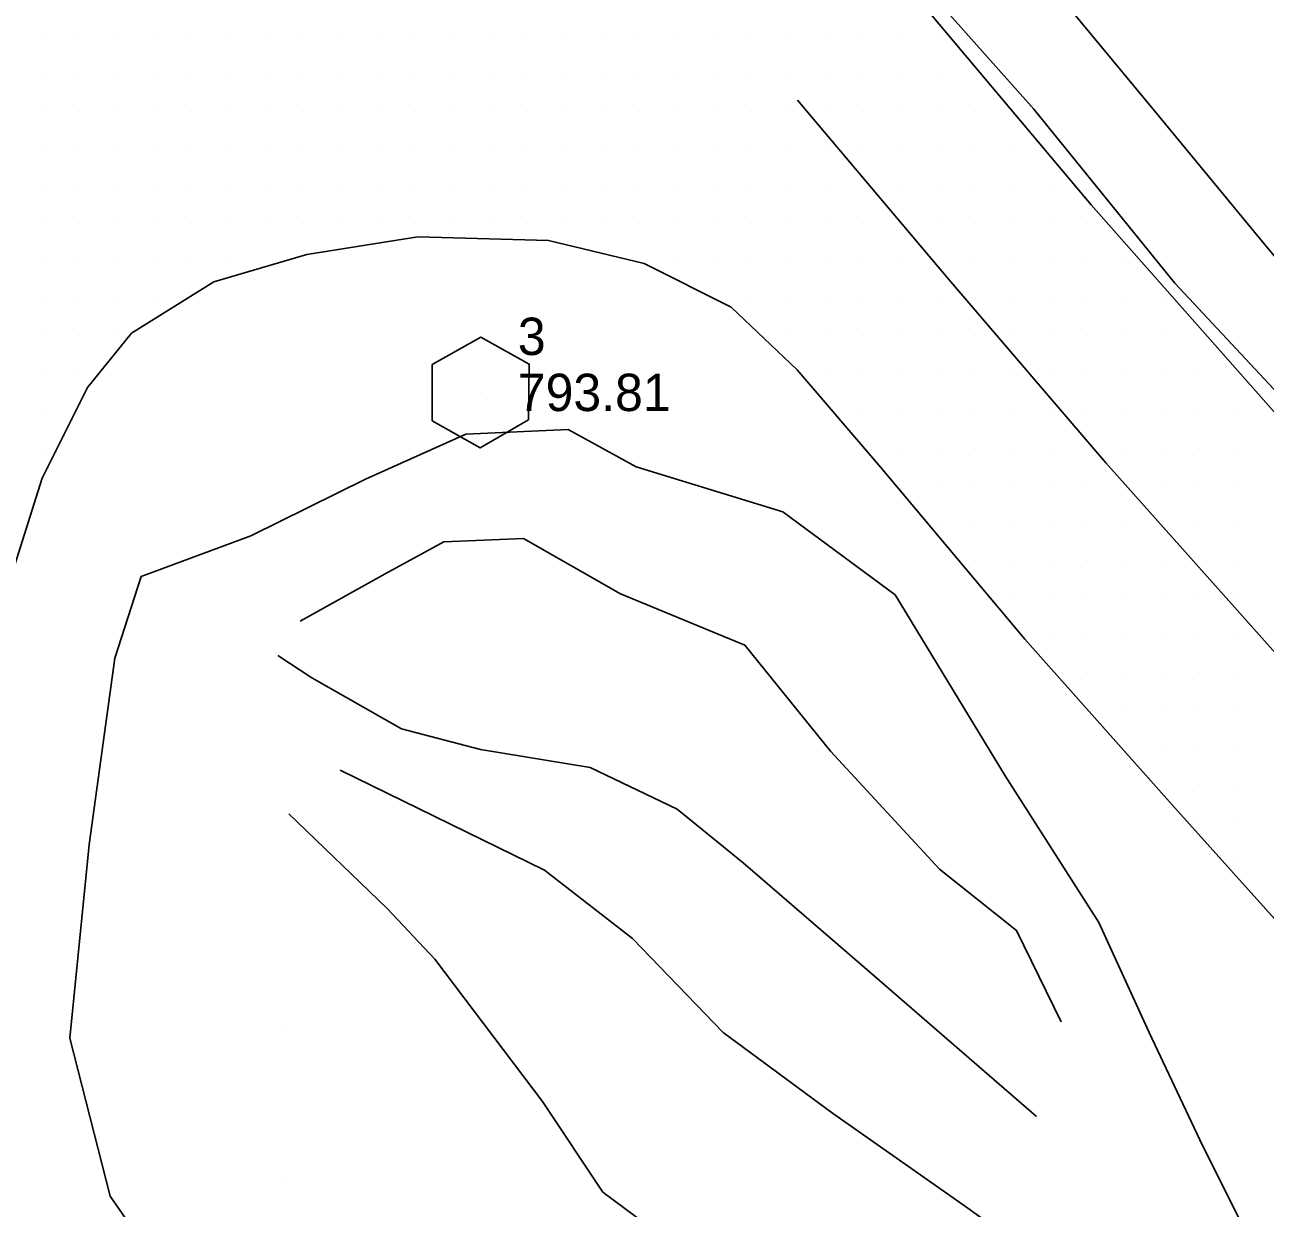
# Model space of a CAD drawing. Extents: x 1762120 to 1766775, y 709485 to 712965.
# Drawn here: x 1764097.6 to 1764180.6, y 711242.9 to 711322.1 of the extents above; entities that cross this region are included whole.
import ezdxf

# ---------------------------------------------------------------- set-up
doc = ezdxf.new("R2010")
doc.units = 0
for name, color, linetype in [('CTL Primary Horizontal and Vertical CELL', 7, 'Continuous'), ('CTL Primary Horizontal and Vertical Cogo Elevation', 7, 'Continuous'), ('CTL Primary Horizontal and Vertical Cogo Number', 7, 'Continuous'), ('Exist DTM QL2 LIDAR Elevation Point', 7, 'Continuous'), ('Exist DTM Scan Elevation Point', 7, 'Continuous'), ('Exist Roads EOP', 7, 'Continuous'), ('Exist Roads EOT', 7, 'Continuous'), ('PH Exist DTM Breakline', 7, 'Continuous')]:
    doc.layers.add(name, color=color, linetype=linetype)

msp = doc.modelspace()

# ---------------------------------------------------------------- linework, layer by layer
at = {"layer": 'CTL Primary Horizontal and Vertical CELL'}
msp.add_line((1764128.102, 711297.478), (1764128.102, 711297.478), dxfattribs=at)
msp.add_lwpolyline([(1764124.871, 711299.35), (1764128.121, 711301.162), (1764131.371, 711299.375), (1764131.321, 711295.65), (1764128.071, 711293.762), (1764124.871, 711295.575)], close=True, dxfattribs=at)
at = {"layer": 'Exist DTM QL2 LIDAR Elevation Point'}
for p, q in [((1764114.998, 711254.994), (1764114.998, 711254.994)), ((1764114.998, 711244.993), (1764114.998, 711244.993))]:
    msp.add_line(p, q, dxfattribs=at)
at = {"layer": 'Exist DTM Scan Elevation Point'}
for p, q in [((1764098.75, 711321.25), (1764098.75, 711321.25)), ((1764101.25, 711321.25), (1764101.25, 711321.25)), ((1764103.75, 711321.25), (1764103.75, 711321.25)), ((1764106.25, 711321.25), (1764106.25, 711321.25)), ((1764108.75, 711321.25), (1764108.75, 711321.25)), ((1764111.25, 711321.25), (1764111.25, 711321.25)), ((1764113.75, 711321.25), (1764113.75, 711321.25)), ((1764116.25, 711321.25), (1764116.25, 711321.25)), ((1764118.75, 711321.25), (1764118.75, 711321.25)), ((1764121.25, 711321.25), (1764121.25, 711321.25)), ((1764123.75, 711321.25), (1764123.75, 711321.25)), ((1764126.25, 711321.25), (1764126.25, 711321.25)), ((1764128.75, 711321.25), (1764128.75, 711321.25)), ((1764131.25, 711321.25), (1764131.25, 711321.25)), ((1764133.75, 711321.25), (1764133.75, 711321.25)), ((1764136.25, 711321.25), (1764136.25, 711321.25)), ((1764138.75, 711321.25), (1764138.75, 711321.25)), ((1764141.25, 711321.25), (1764141.25, 711321.25)), ((1764143.75, 711321.25), (1764143.75, 711321.25)), ((1764146.25, 711321.25), (1764146.25, 711321.25)), ((1764148.75, 711321.25), (1764148.75, 711321.25)), ((1764151.25, 711321.25), (1764151.25, 711321.25)), ((1764153.75, 711321.25), (1764153.75, 711321.25)), ((1764156.25, 711321.25), (1764156.25, 711321.25)), ((1764158.75, 711321.25), (1764158.75, 711321.25)), ((1764098.75, 711318.75), (1764098.75, 711318.75)), ((1764101.25, 711318.75), (1764101.25, 711318.75)), ((1764103.75, 711318.75), (1764103.75, 711318.75)), ((1764106.25, 711318.75), (1764106.25, 711318.75)), ((1764108.75, 711318.75), (1764108.75, 711318.75)), ((1764111.25, 711318.75), (1764111.25, 711318.75)), ((1764113.75, 711318.75), (1764113.75, 711318.75)), ((1764116.25, 711318.75), (1764116.25, 711318.75)), ((1764118.75, 711318.75), (1764118.75, 711318.75)), ((1764121.25, 711318.75), (1764121.25, 711318.75)), ((1764123.75, 711318.75), (1764123.75, 711318.75)), ((1764126.25, 711318.75), (1764126.25, 711318.75)), ((1764128.75, 711318.75), (1764128.75, 711318.75)), ((1764131.25, 711318.75), (1764131.25, 711318.75)), ((1764133.75, 711318.75), (1764133.75, 711318.75)), ((1764136.25, 711318.75), (1764136.25, 711318.75)), ((1764138.75, 711318.75), (1764138.75, 711318.75)), ((1764141.25, 711318.75), (1764141.25, 711318.75)), ((1764143.75, 711318.75), (1764143.75, 711318.75)), ((1764146.25, 711318.75), (1764146.25, 711318.75)), ((1764148.75, 711318.75), (1764148.75, 711318.75)), ((1764151.25, 711318.75), (1764151.25, 711318.75)), ((1764153.75, 711318.75), (1764153.75, 711318.75)), ((1764156.25, 711318.75), (1764156.25, 711318.75)), ((1764158.75, 711318.75), (1764158.75, 711318.75)), ((1764098.75, 711316.25), (1764098.75, 711316.25)), ((1764101.25, 711316.25), (1764101.25, 711316.25)), ((1764103.75, 711316.25), (1764103.75, 711316.25)), ((1764106.25, 711316.25), (1764106.25, 711316.25)), ((1764108.75, 711316.25), (1764108.75, 711316.25)), ((1764111.25, 711316.25), (1764111.25, 711316.25)), ((1764113.75, 711316.25), (1764113.75, 711316.25)), ((1764116.25, 711316.25), (1764116.25, 711316.25)), ((1764118.75, 711316.25), (1764118.75, 711316.25)), ((1764121.25, 711316.25), (1764121.25, 711316.25)), ((1764123.75, 711316.25), (1764123.75, 711316.25)), ((1764126.25, 711316.25), (1764126.25, 711316.25)), ((1764128.75, 711316.25), (1764128.75, 711316.25)), ((1764131.25, 711316.25), (1764131.25, 711316.25)), ((1764133.75, 711316.25), (1764133.75, 711316.25)), ((1764136.25, 711316.25), (1764136.25, 711316.25)), ((1764138.75, 711316.25), (1764138.75, 711316.25)), ((1764141.25, 711316.25), (1764141.25, 711316.25)), ((1764143.75, 711316.25), (1764143.75, 711316.25)), ((1764146.25, 711316.25), (1764146.25, 711316.25)), ((1764148.75, 711316.25), (1764148.75, 711316.25)), ((1764151.25, 711316.25), (1764151.25, 711316.25)), ((1764153.75, 711316.25), (1764153.75, 711316.25)), ((1764156.25, 711316.25), (1764156.25, 711316.25)), ((1764158.75, 711316.25), (1764158.75, 711316.25)), ((1764161.25, 711316.25), (1764161.25, 711316.25)), ((1764098.75, 711313.75), (1764098.75, 711313.75)), ((1764101.25, 711313.75), (1764101.25, 711313.75)), ((1764103.75, 711313.75), (1764103.75, 711313.75)), ((1764106.25, 711313.75), (1764106.25, 711313.75)), ((1764108.75, 711313.75), (1764108.75, 711313.75)), ((1764111.25, 711313.75), (1764111.25, 711313.75)), ((1764113.75, 711313.75), (1764113.75, 711313.75)), ((1764116.25, 711313.75), (1764116.25, 711313.75)), ((1764118.75, 711313.75), (1764118.75, 711313.75)), ((1764121.25, 711313.75), (1764121.25, 711313.75)), ((1764123.75, 711313.75), (1764123.75, 711313.75)), ((1764126.25, 711313.75), (1764126.25, 711313.75)), ((1764128.75, 711313.75), (1764128.75, 711313.75)), ((1764131.25, 711313.75), (1764131.25, 711313.75)), ((1764133.75, 711313.75), (1764133.75, 711313.75)), ((1764136.25, 711313.75), (1764136.25, 711313.75)), ((1764138.75, 711313.75), (1764138.75, 711313.75)), ((1764141.25, 711313.75), (1764141.25, 711313.75)), ((1764143.75, 711313.75), (1764143.75, 711313.75)), ((1764146.25, 711313.75), (1764146.25, 711313.75)), ((1764148.75, 711313.75), (1764148.75, 711313.75)), ((1764151.25, 711313.75), (1764151.25, 711313.75)), ((1764153.75, 711313.75), (1764153.75, 711313.75)), ((1764156.25, 711313.75), (1764156.25, 711313.75)), ((1764158.75, 711313.75), (1764158.75, 711313.75)), ((1764161.25, 711313.75), (1764161.25, 711313.75)), ((1764163.75, 711313.75), (1764163.75, 711313.75)), ((1764098.75, 711311.25), (1764098.75, 711311.25)), ((1764101.25, 711311.25), (1764101.25, 711311.25)), ((1764103.75, 711311.25), (1764103.75, 711311.25)), ((1764106.25, 711311.25), (1764106.25, 711311.25)), ((1764108.75, 711311.25), (1764108.75, 711311.25)), ((1764111.25, 711311.25), (1764111.25, 711311.25)), ((1764113.75, 711311.25), (1764113.75, 711311.25)), ((1764116.25, 711311.25), (1764116.25, 711311.25)), ((1764118.75, 711311.25), (1764118.75, 711311.25)), ((1764121.25, 711311.25), (1764121.25, 711311.25)), ((1764123.75, 711311.25), (1764123.75, 711311.25)), ((1764126.25, 711311.25), (1764126.25, 711311.25)), ((1764128.75, 711311.25), (1764128.75, 711311.25)), ((1764131.25, 711311.25), (1764131.25, 711311.25)), ((1764133.75, 711311.25), (1764133.75, 711311.25)), ((1764136.25, 711311.25), (1764136.25, 711311.25)), ((1764138.75, 711311.25), (1764138.75, 711311.25)), ((1764141.25, 711311.25), (1764141.25, 711311.25)), ((1764143.75, 711311.25), (1764143.75, 711311.25)), ((1764146.25, 711311.25), (1764146.25, 711311.25)), ((1764148.75, 711311.25), (1764148.75, 711311.25)), ((1764151.25, 711311.25), (1764151.25, 711311.25)), ((1764156.25, 711311.25), (1764156.25, 711311.25)), ((1764158.75, 711311.25), (1764158.75, 711311.25)), ((1764161.25, 711311.25), (1764161.25, 711311.25)), ((1764163.75, 711311.25), (1764163.75, 711311.25)), ((1764166.25, 711311.25), (1764166.25, 711311.25)), ((1764098.75, 711308.75), (1764098.75, 711308.75)), ((1764101.25, 711308.75), (1764101.25, 711308.75)), ((1764103.75, 711308.75), (1764103.75, 711308.75)), ((1764106.25, 711308.75), (1764106.25, 711308.75)), ((1764108.75, 711308.75), (1764108.75, 711308.75)), ((1764111.25, 711308.75), (1764111.25, 711308.75)), ((1764113.75, 711308.75), (1764113.75, 711308.75)), ((1764116.25, 711308.75), (1764116.25, 711308.75)), ((1764118.75, 711308.75), (1764118.75, 711308.75)), ((1764121.25, 711308.75), (1764121.25, 711308.75)), ((1764123.75, 711308.75), (1764123.75, 711308.75)), ((1764126.25, 711308.75), (1764126.25, 711308.75)), ((1764128.75, 711308.75), (1764128.75, 711308.75)), ((1764131.25, 711308.75), (1764131.25, 711308.75)), ((1764133.75, 711308.75), (1764133.75, 711308.75)), ((1764136.25, 711308.75), (1764136.25, 711308.75)), ((1764138.75, 711308.75), (1764138.75, 711308.75)), ((1764141.25, 711308.75), (1764141.25, 711308.75)), ((1764143.75, 711308.75), (1764143.75, 711308.75)), ((1764146.25, 711308.75), (1764146.25, 711308.75)), ((1764148.75, 711308.75), (1764148.75, 711308.75)), ((1764151.25, 711308.75), (1764151.25, 711308.75)), ((1764153.75, 711308.75), (1764153.75, 711308.75)), ((1764158.75, 711308.75), (1764158.75, 711308.75)), ((1764161.25, 711308.75), (1764161.25, 711308.75)), ((1764163.75, 711308.75), (1764163.75, 711308.75)), ((1764166.25, 711308.75), (1764166.25, 711308.75)), ((1764168.75, 711308.75), (1764168.75, 711308.75)), ((1764098.75, 711306.25), (1764098.75, 711306.25)), ((1764101.25, 711306.25), (1764101.25, 711306.25)), ((1764103.75, 711306.25), (1764103.75, 711306.25)), ((1764106.25, 711306.25), (1764106.25, 711306.25)), ((1764108.75, 711306.25), (1764108.75, 711306.25)), ((1764111.25, 711306.25), (1764111.25, 711306.25)), ((1764141.25, 711306.25), (1764141.25, 711306.25)), ((1764143.75, 711306.25), (1764143.75, 711306.25)), ((1764146.25, 711306.25), (1764146.25, 711306.25)), ((1764148.75, 711306.25), (1764148.75, 711306.25)), ((1764151.25, 711306.25), (1764151.25, 711306.25)), ((1764153.75, 711306.25), (1764153.75, 711306.25)), ((1764156.25, 711306.25), (1764156.25, 711306.25)), ((1764161.25, 711306.25), (1764161.25, 711306.25)), ((1764163.75, 711306.25), (1764163.75, 711306.25)), ((1764166.25, 711306.25), (1764166.25, 711306.25)), ((1764168.75, 711306.25), (1764168.75, 711306.25)), ((1764171.25, 711306.25), (1764171.25, 711306.25)), ((1764098.75, 711303.75), (1764098.75, 711303.75)), ((1764101.25, 711303.75), (1764101.25, 711303.75)), ((1764103.75, 711303.75), (1764103.75, 711303.75)), ((1764106.25, 711303.75), (1764106.25, 711303.75)), ((1764146.25, 711303.75), (1764146.25, 711303.75)), ((1764148.75, 711303.75), (1764148.75, 711303.75)), ((1764151.25, 711303.75), (1764151.25, 711303.75)), ((1764153.75, 711303.75), (1764153.75, 711303.75)), ((1764156.25, 711303.75), (1764156.25, 711303.75)), ((1764158.75, 711303.75), (1764158.75, 711303.75)), ((1764161.25, 711303.75), (1764161.25, 711303.75)), ((1764163.75, 711303.75), (1764163.75, 711303.75)), ((1764166.25, 711303.75), (1764166.25, 711303.75)), ((1764168.75, 711303.75), (1764168.75, 711303.75)), ((1764171.25, 711303.75), (1764171.25, 711303.75)), ((1764173.75, 711303.75), (1764173.75, 711303.75)), ((1764098.75, 711301.25), (1764098.75, 711301.25)), ((1764101.25, 711301.25), (1764101.25, 711301.25)), ((1764103.75, 711301.25), (1764103.75, 711301.25)), ((1764148.75, 711301.25), (1764148.75, 711301.25)), ((1764151.25, 711301.25), (1764151.25, 711301.25)), ((1764153.75, 711301.25), (1764153.75, 711301.25)), ((1764156.25, 711301.25), (1764156.25, 711301.25)), ((1764158.75, 711301.25), (1764158.75, 711301.25)), ((1764161.25, 711301.25), (1764161.25, 711301.25)), ((1764163.75, 711301.25), (1764163.75, 711301.25)), ((1764166.25, 711301.25), (1764166.25, 711301.25)), ((1764168.75, 711301.25), (1764168.75, 711301.25)), ((1764171.25, 711301.25), (1764171.25, 711301.25)), ((1764173.75, 711301.25), (1764173.75, 711301.25)), ((1764098.75, 711298.75), (1764098.75, 711298.75)), ((1764101.25, 711298.75), (1764101.25, 711298.75)), ((1764151.25, 711298.75), (1764151.25, 711298.75)), ((1764153.75, 711298.75), (1764153.75, 711298.75)), ((1764156.25, 711298.75), (1764156.25, 711298.75)), ((1764158.75, 711298.75), (1764158.75, 711298.75)), ((1764161.25, 711298.75), (1764161.25, 711298.75)), ((1764163.75, 711298.75), (1764163.75, 711298.75)), ((1764166.25, 711298.75), (1764166.25, 711298.75)), ((1764168.75, 711298.75), (1764168.75, 711298.75)), ((1764171.25, 711298.75), (1764171.25, 711298.75)), ((1764173.75, 711298.75), (1764173.75, 711298.75)), ((1764176.25, 711298.75), (1764176.25, 711298.75)), ((1764098.75, 711296.25), (1764098.75, 711296.25)), ((1764153.75, 711296.25), (1764153.75, 711296.25)), ((1764156.25, 711296.25), (1764156.25, 711296.25)), ((1764158.75, 711296.25), (1764158.75, 711296.25)), ((1764161.25, 711296.25), (1764161.25, 711296.25)), ((1764163.75, 711296.25), (1764163.75, 711296.25)), ((1764166.25, 711296.25), (1764166.25, 711296.25)), ((1764168.75, 711296.25), (1764168.75, 711296.25)), ((1764171.25, 711296.25), (1764171.25, 711296.25)), ((1764173.75, 711296.25), (1764173.75, 711296.25)), ((1764176.25, 711296.25), (1764176.25, 711296.25)), ((1764178.75, 711296.25), (1764178.75, 711296.25)), ((1764098.75, 711293.75), (1764098.75, 711293.75)), ((1764156.25, 711293.75), (1764156.25, 711293.75)), ((1764158.75, 711293.75), (1764158.75, 711293.75)), ((1764161.25, 711293.75), (1764161.25, 711293.75)), ((1764163.75, 711293.75), (1764163.75, 711293.75)), ((1764166.25, 711293.75), (1764166.25, 711293.75)), ((1764171.25, 711293.75), (1764171.25, 711293.75)), ((1764173.75, 711293.75), (1764173.75, 711293.75)), ((1764176.25, 711293.75), (1764176.25, 711293.75)), ((1764178.75, 711293.75), (1764178.75, 711293.75)), ((1764158.75, 711291.25), (1764158.75, 711291.25)), ((1764161.25, 711291.25), (1764161.25, 711291.25)), ((1764163.75, 711291.25), (1764163.75, 711291.25)), ((1764166.25, 711291.25), (1764166.25, 711291.25)), ((1764168.75, 711291.25), (1764168.75, 711291.25)), ((1764173.75, 711291.25), (1764173.75, 711291.25)), ((1764176.25, 711291.25), (1764176.25, 711291.25)), ((1764178.75, 711291.25), (1764178.75, 711291.25)), ((1764158.75, 711288.75), (1764158.75, 711288.75)), ((1764161.25, 711288.75), (1764161.25, 711288.75)), ((1764163.75, 711288.75), (1764163.75, 711288.75)), ((1764166.25, 711288.75), (1764166.25, 711288.75)), ((1764168.75, 711288.75), (1764168.75, 711288.75)), ((1764171.25, 711288.75), (1764171.25, 711288.75)), ((1764176.25, 711288.75), (1764176.25, 711288.75)), ((1764178.75, 711288.75), (1764178.75, 711288.75)), ((1764161.25, 711286.25), (1764161.25, 711286.25)), ((1764163.75, 711286.25), (1764163.75, 711286.25)), ((1764166.25, 711286.25), (1764166.25, 711286.25)), ((1764168.75, 711286.25), (1764168.75, 711286.25)), ((1764171.25, 711286.25), (1764171.25, 711286.25)), ((1764173.75, 711286.25), (1764173.75, 711286.25)), ((1764178.75, 711286.25), (1764178.75, 711286.25)), ((1764163.75, 711283.75), (1764163.75, 711283.75)), ((1764166.25, 711283.75), (1764166.25, 711283.75)), ((1764168.75, 711283.75), (1764168.75, 711283.75)), ((1764171.25, 711283.75), (1764171.25, 711283.75)), ((1764173.75, 711283.75), (1764173.75, 711283.75)), ((1764176.25, 711283.75), (1764176.25, 711283.75)), ((1764178.75, 711283.75), (1764178.75, 711283.75)), ((1764166.25, 711281.25), (1764166.25, 711281.25)), ((1764168.75, 711281.25), (1764168.75, 711281.25)), ((1764171.25, 711281.25), (1764171.25, 711281.25)), ((1764173.75, 711281.25), (1764173.75, 711281.25)), ((1764176.25, 711281.25), (1764176.25, 711281.25)), ((1764178.75, 711281.25), (1764178.75, 711281.25)), ((1764168.75, 711278.75), (1764168.75, 711278.75)), ((1764171.25, 711278.75), (1764171.25, 711278.75)), ((1764173.75, 711278.75), (1764173.75, 711278.75)), ((1764176.25, 711278.75), (1764176.25, 711278.75)), ((1764178.75, 711278.75), (1764178.75, 711278.75)), ((1764171.25, 711276.25), (1764171.25, 711276.25)), ((1764173.75, 711276.25), (1764173.75, 711276.25)), ((1764176.25, 711276.25), (1764176.25, 711276.25)), ((1764178.75, 711276.25), (1764178.75, 711276.25)), ((1764173.75, 711273.75), (1764173.75, 711273.75)), ((1764176.25, 711273.75), (1764176.25, 711273.75)), ((1764178.75, 711273.75), (1764178.75, 711273.75)), ((1764176.25, 711271.25), (1764176.25, 711271.25)), ((1764178.75, 711271.25), (1764178.75, 711271.25)), ((1764176.25, 711268.75), (1764176.25, 711268.75)), ((1764178.75, 711268.75), (1764178.75, 711268.75)), ((1764178.75, 711266.25), (1764178.75, 711266.25))]:
    msp.add_line(p, q, dxfattribs=at)
at = {"layer": 'Exist Roads EOP'}
for points in [[(1764117.529, 711374.002), (1764127.05, 711362.399), (1764136.08, 711350.786), (1764145.569, 711339.164), (1764155.174, 711327.647), (1764165.124, 711316.428), (1764174.572, 711304.779), (1764184.682, 711293.959), (1764194.184, 711282.308), (1764204.192, 711271.143), (1764214.382, 711260.143), (1764224.945, 711249.5), (1764235.495, 711238.851), (1764246.055, 711228.211), (1764256.704, 711217.661), (1764267.338, 711207.575), (1764278.311, 711197.394), (1764289.223, 711187.138), (1764300.292, 711177.059), (1764311.462, 711167.082), (1764319.579, 711159.898)], [(1764226.509, 711215.389), (1764215.757, 711226.091), (1764205.433, 711236.961), (1764195.183, 711247.899), (1764184.59, 711258.527), (1764174.568, 711269.675), (1764164.538, 711280.97), (1764154.902, 711292.458), (1764149.286, 711298.982), (1764144.881, 711303.189), (1764139.063, 711306.107), (1764132.644, 711307.642), (1764123.914, 711307.881), (1764116.488, 711306.712), (1764110.261, 711304.88), (1764104.745, 711301.438), (1764101.805, 711297.812), (1764098.757, 711291.73), (1764096.91, 711285.871)]]:
    msp.add_lwpolyline(points, dxfattribs=at)
at = {"layer": 'Exist Roads EOT'}
for points in [[(1764318.567, 711159.132), (1764305.725, 711170.257), (1764292.499, 711182.07), (1764267.302, 711205.818), (1764240.381, 711232.577), (1764221.219, 711252.296), (1764205.482, 711269.302), (1764192.177, 711283.771), (1764168.973, 711310.034), (1764143.07, 711340.825), (1764121.056, 711368.35), (1764116.114, 711374.819)], [(1764149.316, 711317.031), (1764159.582, 711304.879), (1764169.951, 711292.771), (1764193.41, 711266.469), (1764214.31, 711244.118), (1764244.217, 711213.809), (1764278.502, 711180.659), (1764294.071, 711166.461), (1764311.308, 711151.237)]]:
    msp.add_lwpolyline(points, dxfattribs=at)
at = {"layer": 'PH Exist DTM Breakline'}
for points in [[(1764165.432, 711325.732), (1764173.203, 711316.323), (1764180.662, 711307.276), (1764191.146, 711294.755), (1764200.37, 711284.311), (1764212.168, 711272.248), (1764221.564, 711262.725), (1764227.455, 711255.364)], [(1764107.415, 711237.774), (1764103.324, 711243.707), (1764100.618, 711254.261), (1764101.915, 711267.224), (1764103.637, 711279.687), (1764105.398, 711285.17), (1764112.73, 711287.874), (1764120.409, 711291.663), (1764127.118, 711294.673), (1764133.965, 711294.985), (1764138.53, 711292.507), (1764148.331, 711289.496), (1764155.85, 711283.943), (1764163.211, 711271.815), (1764169.48, 711262.014), (1764172.864, 711254.644), (1764176.238, 711247.472), (1764179.986, 711239.956)], [(1764116.034, 711282.18), (1764121.93, 711285.449), (1764125.645, 711287.484), (1764130.988, 711287.701), (1764137.472, 711284.008), (1764145.795, 711280.568), (1764151.516, 711273.474), (1764158.819, 711265.577), (1764163.977, 711261.48), (1764166.974, 711255.354)], [(1764165.302, 711249.024), (1764153.806, 711258.999), (1764145.687, 711265.994), (1764141.256, 711269.596), (1764135.445, 711272.383), (1764128.114, 711273.595), (1764122.821, 711274.968), (1764116.821, 711278.383), (1764114.534, 711279.881)], [(1764118.719, 711272.198), (1764132.389, 711265.506), (1764138.283, 711260.945), (1764144.352, 711254.646), (1764151.666, 711249.258), (1764160.559, 711242.999), (1764167.54, 711238.002), (1764176.228, 711231.783)], [(1764115.271, 711269.282), (1764121.857, 711262.955), (1764125.05, 711259.568), (1764132.263, 711250.034), (1764136.297, 711243.97), (1764148.516, 711234.888)]]:
    msp.add_lwpolyline(points, dxfattribs=at)

# ---------------------------------------------------------------- texts
at = {"layer": 'CTL Primary Horizontal and Vertical Cogo Elevation'}
msp.add_text('793.81', height=2.5, dxfattribs=at).set_placement((1764130.602, 711296.228))
at = {"layer": 'CTL Primary Horizontal and Vertical Cogo Number'}
msp.add_text('3', height=2.5, dxfattribs=at).set_placement((1764130.602, 711299.978))

doc.saveas('drawing.dxf')
